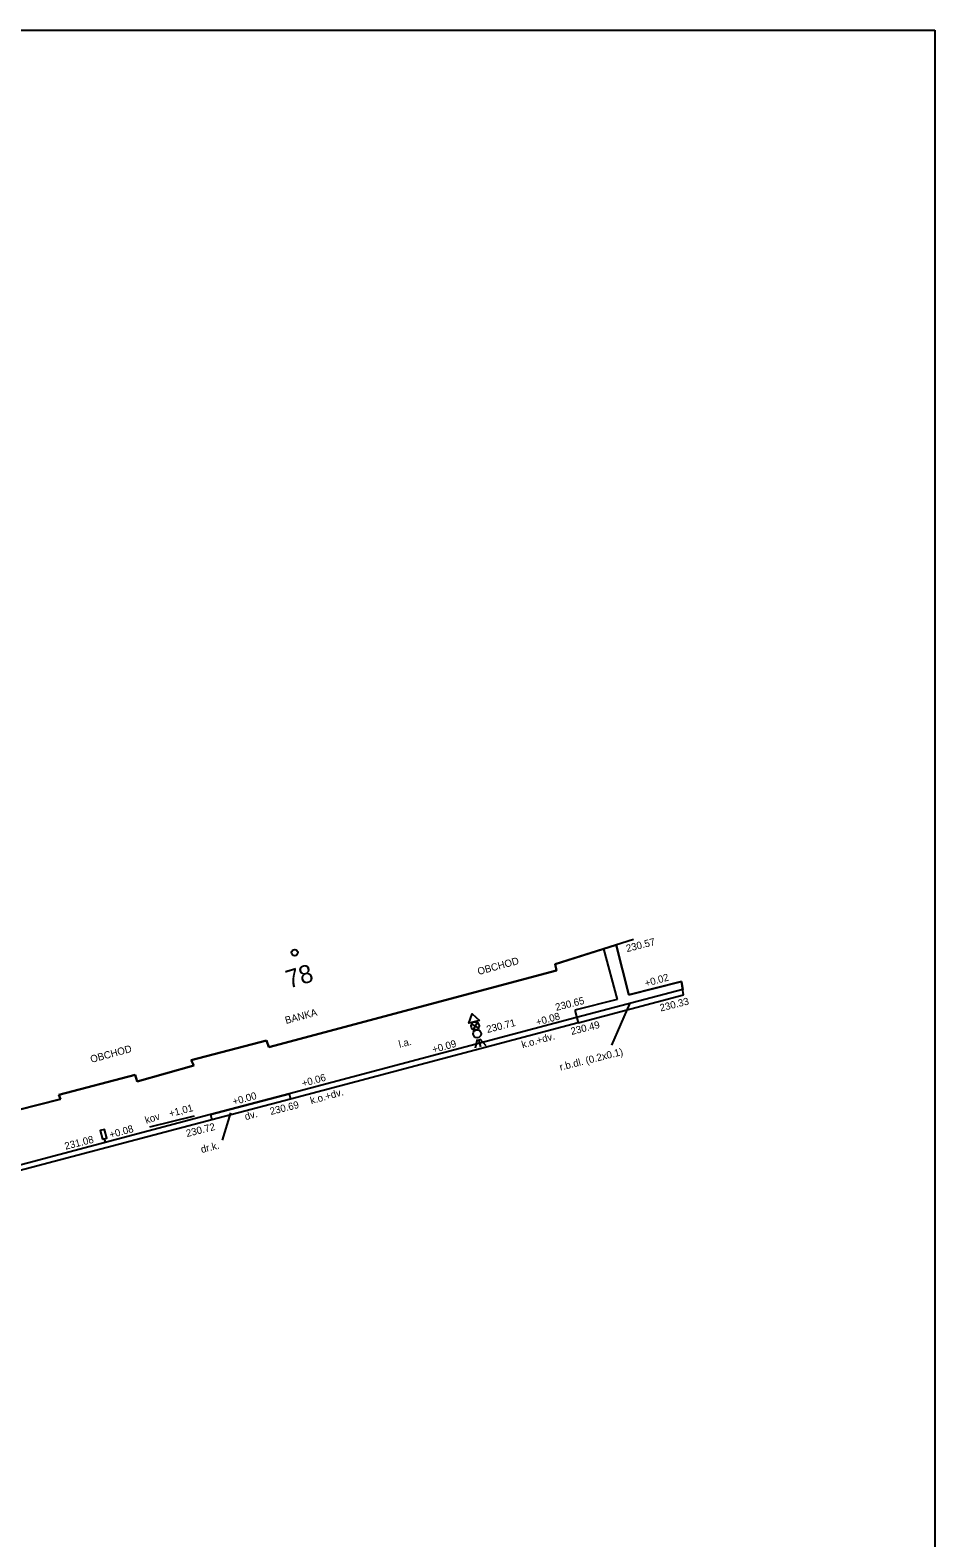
# Model space of a CAD drawing. Extents: x -598874 to -598664, y -1157512 to -1157364.
# Drawn here: x -598714.5 to -598664.5, y -1157447.8 to -1157364.4 of the extents above; entities that cross this region are included whole.
import ezdxf

# ---------------------------------------------------------------- set-up
doc = ezdxf.new("R2010")
doc.units = 0
for name, color, linetype in [('Vrstva 1', 7, 'Continuous'), ('Vrstva 15', 7, 'Continuous'), ('Vrstva 22', 7, 'Continuous'), ('Vrstva 4', 7, 'Continuous'), ('Vrstva 43', 7, 'Continuous'), ('Vrstva 44', 7, 'Continuous'), ('Vrstva 49', 7, 'Continuous'), ('Vrstva 50', 7, 'Continuous'), ('Vrstva 58', 7, 'Continuous'), ('Vrstva 63', 7, 'Continuous'), ('Vrstva 7', 7, 'Continuous')]:
    doc.layers.add(name, color=color, linetype=linetype)

msp = doc.modelspace()

# ---------------------------------------------------------------- linework, layer by layer
at = {"layer": 'Vrstva 1'}
for p, q in [((-598874.499, -1157364.413), (-598664.499, -1157364.413)), ((-598664.499, -1157364.413), (-598664.499, -1157512.412))]:
    msp.add_line(p, q, dxfattribs=at)
at = {"layer": 'Vrstva 15'}
msp.add_line((-598710.355, -1157425.953), (-598710.416, -1157425.711), dxfattribs=at)
msp.add_lwpolyline([(-598710.537, -1157425.741), (-598710.295, -1157425.68), (-598710.416, -1157425.195), (-598710.659, -1157425.256)], close=True, dxfattribs=at)
msp.add_circle((-598699.9, -1157415.421), 0.175, dxfattribs=at)
at = {"layer": 'Vrstva 22'}
msp.add_line((-598705.466, -1157424.461), (-598707.936, -1157425.071), dxfattribs=at)
at = {"layer": 'Vrstva 4'}
for p, q in [((-598681.166, -1157414.691), (-598685.496, -1157416.063)), ((-598685.496, -1157416.063), (-598685.415, -1157416.402)), ((-598685.415, -1157416.402), (-598701.326, -1157420.651)), ((-598701.453, -1157420.281), (-598705.622, -1157421.362)), ((-598701.326, -1157420.651), (-598701.453, -1157420.281)), ((-598705.484, -1157421.658), (-598708.622, -1157422.549)), ((-598705.622, -1157421.362), (-598705.484, -1157421.658)), ((-598708.724, -1157422.182), (-598712.946, -1157423.281)), ((-598708.622, -1157422.549), (-598708.724, -1157422.182)), ((-598712.851, -1157423.521), (-598720.711, -1157425.495)), ((-598712.946, -1157423.281), (-598712.851, -1157423.521)), ((-598712.851, -1157423.521), (-598712.851, -1157423.521))]:
    msp.add_line(p, q, dxfattribs=at)
at = {"layer": 'Vrstva 44'}
for p, q in [((-598690.117, -1157419.356), (-598689.729, -1157419.588)), ((-598689.807, -1157419.278), (-598690.04, -1157419.666)), ((-598689.814, -1157420.218), (-598689.922, -1157420.709)), ((-598689.741, -1157420.199), (-598689.631, -1157420.636)), ((-598689.668, -1157420.181), (-598689.34, -1157420.563))]:
    msp.add_line(p, q, dxfattribs=at)
msp.add_lwpolyline([(-598689.685, -1157419.174), (-598690.269, -1157419.32), (-598690.09, -1157418.804)], close=True, dxfattribs=at)
for centre, radius in [((-598689.923, -1157419.472), 0.226), ((-598689.814, -1157419.908), 0.224)]:
    msp.add_circle(centre, radius, dxfattribs=at)
at = {"layer": 'Vrstva 49'}
for p, q in [((-598682.372, -1157420.546), (-598681.37, -1157418.26)), ((-598703.897, -1157425.782), (-598703.44, -1157424.277))]:
    msp.add_line(p, q, dxfattribs=at)
at = {"layer": 'Vrstva 63'}
for p, q in [((-598685.496, -1157416.063), (-598682.129, -1157414.996)), ((-598682.129, -1157414.996), (-598681.426, -1157417.761)), ((-598685.415, -1157416.402), (-598685.496, -1157416.063)), ((-598701.326, -1157420.651), (-598685.415, -1157416.402)), ((-598681.426, -1157417.761), (-598678.516, -1157417.021)), ((-598678.516, -1157417.021), (-598678.445, -1157417.453)), ((-598678.445, -1157417.453), (-598684.309, -1157419.016)), ((-598684.309, -1157419.016), (-598700.216, -1157423.226)), ((-598705.622, -1157421.362), (-598701.453, -1157420.281)), ((-598701.453, -1157420.281), (-598701.326, -1157420.651)), ((-598708.622, -1157422.549), (-598705.484, -1157421.658)), ((-598705.484, -1157421.658), (-598705.622, -1157421.362)), ((-598712.946, -1157423.281), (-598708.724, -1157422.182)), ((-598708.724, -1157422.182), (-598708.622, -1157422.549)), ((-598720.711, -1157425.495), (-598712.851, -1157423.521)), ((-598712.851, -1157423.521), (-598712.946, -1157423.281)), ((-598704.553, -1157424.373), (-598700.216, -1157423.226)), ((-598704.553, -1157424.373), (-598725.546, -1157429.929))]:
    msp.add_line(p, q, dxfattribs=at)
at = {"layer": 'Vrstva 7'}
for p, q in [((-598682.823, -1157415.215), (-598682.076, -1157418.011)), ((-598681.426, -1157417.761), (-598682.129, -1157414.996)), ((-598678.516, -1157417.021), (-598681.426, -1157417.761)), ((-598678.396, -1157417.751), (-598678.516, -1157417.021)), ((-598684.232, -1157419.306), (-598678.396, -1157417.751)), ((-598682.076, -1157418.011), (-598684.416, -1157418.611)), ((-598684.416, -1157418.611), (-598684.232, -1157419.306)), ((-598684.232, -1157419.306), (-598700.139, -1157423.516)), ((-598700.216, -1157423.226), (-598704.553, -1157424.373)), ((-598700.139, -1157423.516), (-598704.476, -1157424.663)), ((-598700.216, -1157423.226), (-598700.139, -1157423.516)), ((-598704.553, -1157424.373), (-598704.476, -1157424.663)), ((-598704.476, -1157424.663), (-598725.469, -1157430.219))]:
    msp.add_line(p, q, dxfattribs=at)

# ---------------------------------------------------------------- texts
at = {"layer": 'Vrstva 43'}
msp.add_text('78', height=1, rotation=16.54717, dxfattribs=at).set_placement((-598700.218, -1157417.409))
at = {"layer": 'Vrstva 49'}
for s, rotation, p in [('OBCHOD', 15.26118, (-598689.733, -1157416.661)), ('BANKA', 15.26118, (-598700.375, -1157419.369)), ('l.a.', 14.07866, (-598694.101, -1157420.684)), ('k.o.+dv.', 15.59596, (-598687.295, -1157420.712)), ('OBCHOD', 15.26118, (-598711.144, -1157421.52)), ('r.b.dl. (0.2x0.1)', 14.07866, (-598685.201, -1157421.947)), ('k.o.+dv.', 15.59596, (-598698.984, -1157423.803)), ('kov', 18.04305, (-598708.11, -1157424.889)), ('dv.', 15.59596, (-598702.607, -1157424.691)), ('dr.k.', 14.07866, (-598705.04, -1157426.505))]:
    msp.add_text(s, height=0.4, rotation=rotation, dxfattribs=at).set_placement(p)
at = {"layer": 'Vrstva 50'}
for s, rotation, p in [('+0.02', 15.6364, (-598680.481, -1157417.317)), ('+0.08', 15.6364, (-598686.496, -1157419.468)), ('+0.09', 15.6364, (-598692.232, -1157420.982)), ('+0.06', 15.6364, (-598699.446, -1157422.854)), ('+0.00', 15.6364, (-598703.275, -1157423.865)), ('+1,01', 14.72944, (-598706.796, -1157424.52)), ('+0.08', 15.6364, (-598710.085, -1157425.693))]:
    msp.add_text(s, height=0.4, rotation=rotation, dxfattribs=at).set_placement(p)
at = {"layer": 'Vrstva 58'}
for s, p in [('230.57', (-598681.522, -1157415.394)), ('230.65', (-598685.434, -1157418.643)), ('230.33', (-598679.656, -1157418.679)), ('230.71', (-598689.243, -1157419.866)), ('230.49', (-598684.584, -1157419.975)), ('230.69', (-598701.22, -1157424.4)), ('230.72', (-598705.855, -1157425.618)), ('231.08', (-598712.572, -1157426.321))]:
    msp.add_text(s, height=0.4, rotation=14.07866, dxfattribs=at).set_placement(p)

doc.saveas('drawing.dxf')
